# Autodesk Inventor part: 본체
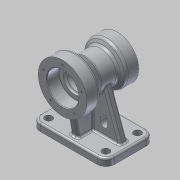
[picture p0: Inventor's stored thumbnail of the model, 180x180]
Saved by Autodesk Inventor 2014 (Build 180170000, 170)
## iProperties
Created: 2015-08
Part Number: 본체
Material: 알루미늄 6061
Document SubType Name: Modeling
Designer: net
Density: 2.71 g/cm^3
Appearance: 알루미늄 - 평지
Mass: 1062.72 g
Surface Area: 748.443 cm^2
Volume: 392.148 cm^3
Author: net
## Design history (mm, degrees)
sketch "스케치1"
  geometry: L1 (-61, 40)-(61, 40); L2 (61, 40)-(61, -40); L3 (61, -40)-(-61, -40); L4 (-61, -40)-(-61, 40); 1 further point
  constraints: 8 end point, 2 parallel, 1 horizontal, 1 perpendicular
  dimensions: "d0" = 122 distance between parallel lines of L2 L4; "d1" = 80 distance between parallel lines of L3 L1; "d2" = 40 distance from line of point (0, 0) L1; "d3" = 61 distance from line of point (0, 0) L4
extrude "돌출1" new body sketch "스케치1" distance "d4" = 12; taper "d5" = 0 deg
fillet "모깎기1" dims "d6" = 14
fillet "모깎기2" dims "d7" = 3
sketch "스케치2"
  geometry: L1 (-47, 37)-(47, 37) reference; L2 (-58, -26)-(-58, 26) reference; C1 r 6 at (-47, 26); C2 r 6 at (-47, -26); C3 r 6 at (47, 26); C4 r 6 at (47, -26); A1 r 11 centre (-47, 26) between (-47, 37) and (-58, 26) reference; 1 further point
  constraints: 4 centre point, 1 coincident, 1 horizontal, 1 vertical, 6 other
  dimensions: "d8" = 12 diameter of C1; "d11" = 52 distance of C1.centre C2.centre; "d14" = 94 distance of C1.centre C3.centre
extrude "돌출2" cut sketch "스케치2" stored distance "d17" = 12; taper "d18" = 0 deg
node "작업 평면1"
sketch "스케치3"
  geometry: L1 (0, 69.591)-(0, -74.026); L2 (35, 40)-(35, 20); L3 (35, 20)-(26, 14.804); L4 (26, 14.804)-(26, -13.315); L5 (26, -13.315)-(40, -30); L6 (40, -30)-(40, -50); L7 (0, 40)-(0, -50); L8 (35, 40)-(20, 40); L9 (20, 40)-(20, 23); L10 (20, 23)-(16, 23); L11 (16, 23)-(16, -27); L12 (26, -30)-(26, -50); L13 (26, -50)-(40, -50); L14 (47, 40)-(-47, 40) reference; L15 (26, -30)-(19, -30); L16 (19, -30)-(19, -27); L17 (19, -27)-(16, -27); 1 further point
  constraints: 32 end point, 8 parallel, 3 perpendicular, 2 point on line, 1 collinear, 1 vertical
  dimensions: "d20" = 70 diameter of L2 L1; "d22" = 60 deg angle of L4 L3; "d24" = 40 deg angle of L4 L5; "d25" = 20 distance of L5.end L6.end; "d26" = 80 diameter of L6 L1; "d27" = 52 diameter of L4 L1; "d29" = 0 distance from line of point (0, 0) L1; "d30" = 40 diameter of L9 L1; "d31" = 0 distance between parallel lines of L8 L14; "d36" = 90 distance between parallel lines of L13 L8; "d37" = 52 diameter of L12 L1; "d38" = 32 diameter of L11 L1; "d39" = 20 distance from line of L2.end L14; "d90" = 17 distance between parallel lines of L10 L14; "d91" = 20 distance between parallel lines of L13 L15; "d92" = 3 distance between parallel lines of L15 L17; "d93" = 38 diameter of L16 L1
revolve "회전1" sketch "스케치3" stored, may be unused: angle "d40" = 90 deg
fillet "모깎기3" dims "d41" = 5
fillet "모깎기4" dims "d42" = 0.3
chamfer "모따기1" distance "d44" = 1; stored, may be unused: second distance "d45" = 2, angle "d46" = 45 deg
sketch "스케치4"
  geometry: L1 (47, 12)-(58, 12) reference; L2 (-58, 12)-(-47, 12) reference; L3 (25.091, 83.185)-(51, 12); L4 (61, 0)-(61, 9) reference; L5 (0, 90)-(0, 0); L6 (-25.091, 83.185)-(-51, 12); L7 (49.162, 12)-(-51, 12); A1 r 26 centre (0, 90) between (-25.091, 83.185) and (25.091, 83.185)
  constraints: 8 end point, 2 point on circle, 2 point on line, 2 symmetric about line, 1 centre point, 1 coincident, 1 collinear, 1 parallel, 2 other
  dimensions: "d47" = 70 deg angle of L3 L1; "d48" = 10 distance from line of L4 L3.end
extrude "돌출3" join sketch "스케치4" stored distance "d49" = 12; taper "d50" = 0 deg
fillet "모깎기6" dims "d51" = 3
sketch "스케치5"
  geometry: L1 (47.807, 12)-(-47.807, 12) reference; L2 (-30, 36)-(-30, 30); L3 (-18, 30)-(-18, 36); L4 (0, 90)-(0, 12); L5 (47, 0)-(-47, 0) reference; A1 r 26 centre (0, 90) between (-23.481, 78.836) and (23.481, 78.836) reference; A2 r 6 centre (-24, 30) between (-30, 30) and (-18, 30); A3 r 6 centre (-24, 36) between (-18, 36) and (-30, 36); 1 further point
  constraints: 6 end point, 4 point on circle, 4 tangent, 2 centre point, 1 midpoint, 1 parallel, 1 perpendicular
  dimensions: "d52" = 18 dimension on A2 A3; "d53" = 12 distance between parallel lines of L3 L2; "d54" = 24 distance from line of L4 A2.centre; "d55" = 30 distance from line of L5 A2.centre
extrude "돌출4" cut sketch "스케치5" stored distance "d56" = 10; taper "d57" = 0 deg
sketch "스케치6"
  geometry: L1 (40, 55)-(22.887, 55) reference; L2 (26, 12)-(37, 12) reference; L3 (30, 55)-(30, 12); L4 (40, 9)-(40, 0) reference; 1 further point
  constraints: 2 end point, 2 point on line, 1 perpendicular
  dimensions: "d58" = 10 distance between parallel lines of L4 L3
feature "리브1" sketch "스케치6" dims "d59" = 1, "d60" = 12, "d61" = 0, "d62" = 0, "d63" = 1, "d64" = 1
sketch "스케치7"
  geometry: L1 (-31.82, 50)-(-50, 50) reference; L2 (-37, 12)-(-26, 12) reference; L3 (-36.7, 50)-(-30, 12); L4 (-40, 0)-(-40, 9) reference; 1 further point
  constraints: 2 end point, 2 point on line
  dimensions: "d66" = 80 deg angle of L3 L2; "d67" = 10 distance from line of L3.end L4
feature "리브2" sketch "스케치7" dims "d68" = 1, "d69" = 12, "d70" = 0, "d71" = 0, "d72" = 1, "d73" = 1
fillet "모깎기7" dims "d74" = 3
fillet "모깎기8" dims "d75" = 3
fillet "모깎기9" dims "d76" = 3
fillet "모깎기10" dims "d94" = 3
sketch "스케치8" dims "d77" = 66
  geometry: L1 (0, 33)-(0, 0); C1 r 27 at (0, 0) reference; C2 r 40 at (0, 0) reference; 6 further points
  constraints: 2 coincident, 2 end point, 1 vertical, 1 vertical alignment, 8 other
  dimensions: "d80" = 360 deg dimension on C1.centre point (0, 33) (derived)
hole "구멍1" sketch "스케치8" at (0, 33), (-31.385, 10.198), (-19.397, -26.698), (19.397, -26.698), (31.385, 10.198) diameter "d82" = 3.242; stored, may be unused: countersink angle "d86" = 90 deg, drill point angle "d88" = 118 deg; dims "d83" = 10, "d84" = 4, "d85" = 2, "d87" = 13
sketch "스케치10" dims "d110" = 54
  geometry: C1 r 21 at (0, 0) reference; C2 r 35 at (0, 0) reference; 7 further points
  constraints: 2 vertical alignment, 1 coincident, 8 other
  dimensions: "d113" = 360 deg dimension on C1.centre point (0, -27) (derived)
hole "구멍3" sketch "스케치10" at (0, -27), (25.679, -8.343), (15.87, 21.843), (-15.87, 21.843), (-25.679, -8.343) diameter "d115" = 3.242; stored, may be unused: countersink angle "d119" = 90 deg, drill point angle "d121" = 118 deg; dims "d116" = 10, "d117" = 4, "d118" = 2, "d120" = 13
sketch "스케치11"
  geometry: L1 (-15.397, 8.002)-(57.397, 8.002); L2 (57.397, 8.002)-(57.397, 1.998); L3 (57.397, 1.998)-(-15.397, 1.998); L4 (-15.397, 1.998)-(-15.397, 8.002); L5 (-15.397, 5)-(57.397, 5); L6 (21, 8.002)-(21, 1.998); L7 (37.119, 21)-(0, 21) reference; L8 (-3, 28)-(-3, 17) reference; 1 further point
  constraints: 4 end point, 4 midpoint, 2 other
  dimensions: "d122" = 16 distance between parallel lines of L5 L7; "d123" = 24 distance between parallel lines of L6 L8
extrude "돌출5" join sketch "스케치11" distance "d124" = 0.5; taper "d125" = 0 deg
node "솔리드1"
mirror "대칭1"
